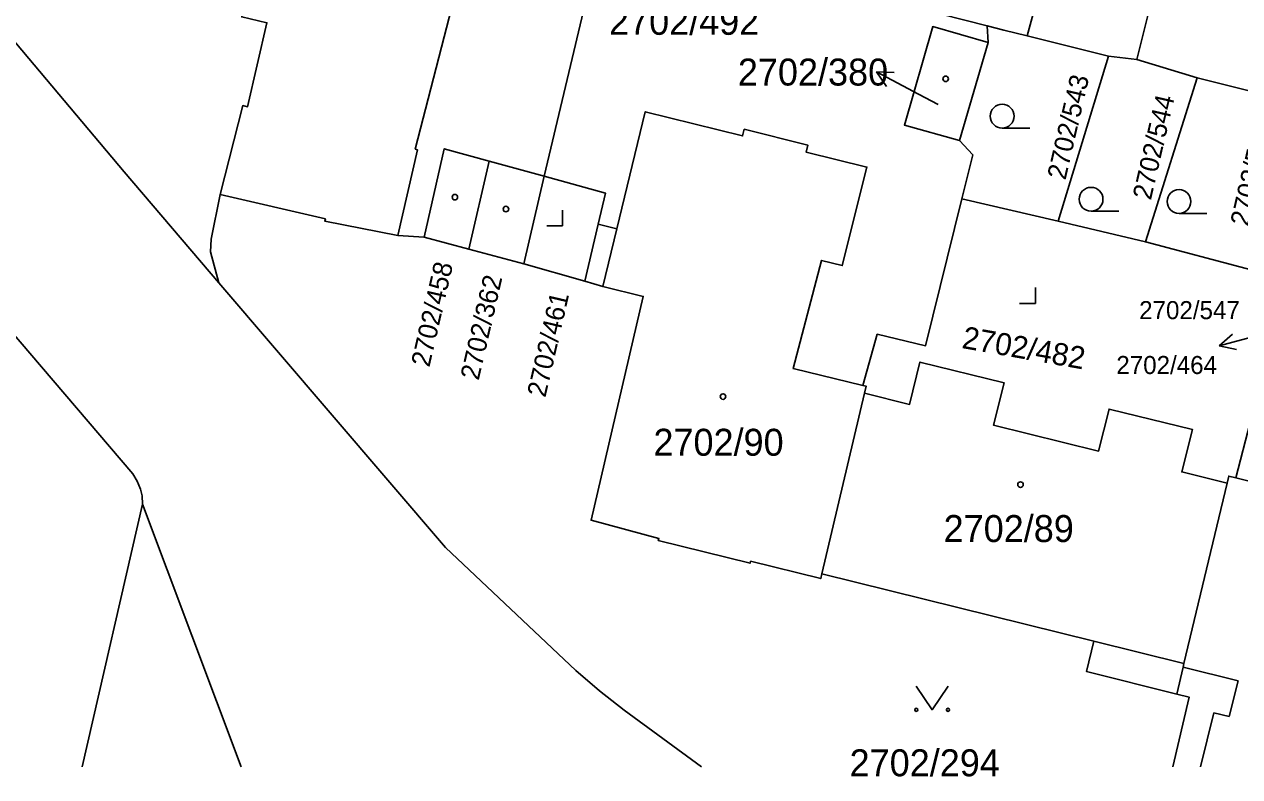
# Model space of a CAD drawing. Extents: x -496682 to -495776, y -1088797 to -1088018.
# Drawn here: x -496634.1 to -496557.4, y -1088570.1 to -1088522.6 of the extents above; entities that cross this region are included whole.
import ezdxf

# ---------------------------------------------------------------- set-up
doc = ezdxf.new("R2010")
doc.units = 0
for name, color, linetype in [('Hranice parcel', 7, 'Continuous'), ('Parcelní čísla', 7, 'Continuous'), ('Pop  PČ popisy', 7, 'Continuous'), ('Vnitřní kresba', 7, 'Continuous'), ('Značky budov', 7, 'Continuous'), ('Značky kultur', 7, 'Continuous')]:
    doc.layers.add(name, color=color, linetype=linetype)

msp = doc.modelspace()

# ---------------------------------------------------------------- linework, layer by layer
at = {"layer": 'Hranice parcel'}
for p, q in [((-496570.83, -1088523.36), (-496567.27, -1088510.42)), ((-496560.68, -1088512.06), (-496563.91, -1088524.85)), ((-496601.3, -1088532.22), (-496597.58, -1088516.58)), ((-496573.34, -1088522.74), (-496577.74, -1088521.62)), ((-496573.29, -1088523.79), (-496573.34, -1088522.74)), ((-496575.1, -1088529.97), (-496573.29, -1088523.79)), ((-496570.83, -1088523.36), (-496565.69, -1088524.64)), ((-496568.87, -1088535.04), (-496565.69, -1088524.64)), ((-496565.69, -1088524.64), (-496563.91, -1088524.85)), ((-496563.91, -1088524.85), (-496560.1, -1088526.02)), ((-496563.36, -1088536.35), (-496560.1, -1088526.02)), ((-496604.78, -1088531.26), (-496606.06, -1088536.81)), ((-496604.78, -1088531.26), (-496601.3, -1088532.22)), ((-496602.58, -1088537.75), (-496601.3, -1088532.22)), ((-496568.87, -1088535.04), (-496574.95, -1088533.64)), ((-496563.36, -1088536.35), (-496568.87, -1088535.04)), ((-496627.27, -1088550.98), (-496639.82, -1088536.3)), ((-496606.06, -1088536.81), (-496608.87, -1088536.05)), ((-496602.58, -1088537.75), (-496606.06, -1088536.81)), ((-496598.73, -1088538.84), (-496602.58, -1088537.75)), ((-496597.6, -1088539.16), (-496598.73, -1088538.84)), ((-496581.09, -1088545.9), (-496583.78, -1088557.29)), ((-496557.65, -1088551.23), (-496556.76, -1088547.74)), ((-496630.453, -1088569.448), (-496626.65, -1088552.9)), ((-496626.65, -1088552.9), (-496620.418, -1088569.448))]:
    msp.add_line(p, q, dxfattribs=at)
for points in [[(-496621.83, -1088538.93), (-496627.8, -1088531.94), (-496637.3, -1088520.68), (-496644.5, -1088512.3)], [(-496619.55, -1088518.48), (-496620.39, -1088522.17), (-496618.8, -1088522.54), (-496620.02, -1088527.84), (-496620.32, -1088527.76), (-496621.75, -1088533.36)], [(-496573.29, -1088523.79), (-496576.78, -1088522.78), (-496578.57, -1088528.99), (-496575.1, -1088529.97)], [(-496573.34, -1088522.74), (-496572.3, -1088523), (-496570.83, -1088523.36)], [(-496560.1, -1088526.02), (-496554.29, -1088527.46), (-496556.58, -1088537.69)], [(-496581.19, -1088545.41), (-496585.6, -1088544.35), (-496583.81, -1088537.52), (-496582.49, -1088537.85), (-496580.94, -1088531.64), (-496584.78, -1088530.69), (-496584.67, -1088530.25), (-496588.68, -1088529.26), (-496588.78, -1088529.68), (-496594.93, -1088528.15), (-496596.72, -1088535.54), (-496597.6, -1088539.16)], [(-496574.95, -1088533.64), (-496574.26, -1088530.86), (-496575.1, -1088529.97)], [(-496608.87, -1088536.05), (-496607.61, -1088530.48), (-496604.78, -1088531.26)], [(-496598.73, -1088538.84), (-496597.9, -1088535.25), (-496597.44, -1088533.28), (-496601.3, -1088532.22)], [(-496621.75, -1088533.36), (-496622.32, -1088536.19), (-496622.36, -1088536.99), (-496621.83, -1088538.93)], [(-496621.75, -1088533.36), (-496615.11, -1088534.91), (-496615.15, -1088535.05), (-496610.53, -1088535.95), (-496608.87, -1088536.05)], [(-496574.95, -1088533.64), (-496577.24, -1088542.91), (-496580.28, -1088542.18), (-496581.19, -1088545.41)], [(-496556.58, -1088537.69), (-496556.68, -1088538.12), (-496563.36, -1088536.35)], [(-496591.366, -1088569.448), (-496596.26, -1088565.89), (-496597.82, -1088564.67), (-496599.31, -1088563.38), (-496607.53, -1088555.63), (-496621.83, -1088538.93)], [(-496597.6, -1088539.16), (-496595.05, -1088539.8), (-496598.34, -1088553.91), (-496594.06, -1088555.06), (-496594.1, -1088555.19), (-496588.31, -1088556.62), (-496588.28, -1088556.49), (-496583.85, -1088557.58), (-496583.78, -1088557.29)], [(-496558.21, -1088551.57), (-496561.07, -1088550.86), (-496560.39, -1088548.19), (-496565.66, -1088546.9), (-496566.32, -1088549.55), (-496572.95, -1088547.91), (-496572.27, -1088545.25), (-496577.59, -1088543.93), (-496578.25, -1088546.6), (-496581.09, -1088545.9)], [(-496581.09, -1088545.9), (-496580.98, -1088545.46), (-496581.19, -1088545.41)], [(-496626.65, -1088552.9), (-496626.679, -1088552.359), (-496626.773, -1088551.939), (-496626.977, -1088551.436), (-496627.27, -1088550.98)], [(-496558.21, -1088551.57), (-496560.94, -1088562.93), (-496560.99, -1088563.18), (-496561.39, -1088564.87)], [(-496557.65, -1088551.23), (-496558.1, -1088551.12), (-496558.21, -1088551.57)], [(-496545.502, -1088569.448), (-496545.94, -1088569.34), (-496542.39, -1088555.02), (-496557.65, -1088551.23)], [(-496583.78, -1088557.29), (-496566.62, -1088561.53), (-496567.09, -1088563.44), (-496561.39, -1088564.87)], [(-496561.39, -1088564.87), (-496560.6, -1088565.07), (-496561.63, -1088569.448)]]:
    msp.add_lwpolyline(points, dxfattribs=at)
at = {"layer": 'Pop  PČ popisy'}
for p, q in [((-496577.69, -1088527.05), (-496580.34, -1088525.641)), ((-496580.34, -1088525.641), (-496579.22, -1088525.669)), ((-496580.34, -1088525.641), (-496579.691, -1088526.553)), ((-496576.45, -1088527.7), (-496577.69, -1088527.05)), ((-496555.81, -1088542.14), (-496558.709, -1088542.917)), ((-496558.709, -1088542.917), (-496557.871, -1088542.174)), ((-496558.709, -1088542.917), (-496557.612, -1088543.141))]:
    msp.add_line(p, q, dxfattribs=at)
at = {"layer": 'Vnitřní kresba'}
for p, q in [((-496605.65, -1088515.77), (-496609.45, -1088530.51)), ((-496609.3, -1088530.55), (-496610.53, -1088535.95)), ((-496609.45, -1088530.51), (-496609.3, -1088530.55)), ((-496597.9, -1088535.25), (-496596.72, -1088535.54)), ((-496560.94, -1088562.93), (-496566.62, -1088561.53)), ((-496560.99, -1088563.18), (-496557.51, -1088564.04)), ((-496557.51, -1088564.04), (-496558.07, -1088566.28)), ((-496559.04, -1088566.04), (-496559.88, -1088569.448)), ((-496558.07, -1088566.28), (-496559.04, -1088566.04))]:
    msp.add_line(p, q, dxfattribs=at)
at = {"layer": 'Značky budov'}
for centre in [(-496575.967, -1088526.079), (-496606.937, -1088533.539), (-496603.717, -1088534.289), (-496590.017, -1088546.109), (-496571.247, -1088551.659)]:
    msp.add_circle(centre, 0.175, dxfattribs=at)
at = {"layer": 'Značky kultur'}
for p, q in [((-496572.403, -1088529.18), (-496570.653, -1088529.18)), ((-496600.14, -1088535.35), (-496600.14, -1088534.35)), ((-496566.793, -1088534.42), (-496565.043, -1088534.42)), ((-496561.243, -1088534.56), (-496559.493, -1088534.56)), ((-496601.141, -1088535.35), (-496600.14, -1088535.35)), ((-496570.3, -1088540.24), (-496570.3, -1088539.24)), ((-496571.301, -1088540.24), (-496570.3, -1088540.24))]:
    msp.add_line(p, q, dxfattribs=at)
msp.add_lwpolyline([(-496577.82, -1088564.359), (-496576.82, -1088565.86), (-496575.82, -1088564.359)], dxfattribs=at)
for centre, radius in [((-496572.403, -1088528.43), 0.75), ((-496566.793, -1088533.67), 0.75), ((-496561.243, -1088533.81), 0.75), ((-496577.82, -1088565.859), 0.1), ((-496575.82, -1088565.859), 0.1)]:
    msp.add_circle(centre, radius, dxfattribs=at)

# ---------------------------------------------------------------- texts
at = {"layer": 'Parcelní čísla'}
for s, height, p in [('2702/492', 1.7, (-496597.21, -1088523.3)), ('2702/380', 1.7, (-496589.08, -1088526.5)), ('2702/547', 1.139, (-496563.758, -1088541.229)), ('2702/464', 1.139, (-496565.198, -1088544.689)), ('2702/90', 1.7, (-496594.408, -1088549.84)), ('2702/89', 1.7, (-496576.098, -1088555.28)), ('2702/294', 1.7, (-496582.03, -1088570.05))]:
    msp.add_text(s, height=height, dxfattribs=at).set_placement(p)
for s, height, rotation, p in [('2702/543', 1.2, 77, (-496568.409, -1088532.5)), ('2702/544', 1.2, 77, (-496563.019, -1088533.77)), ('2702/545', 1.2, 77, (-496556.859, -1088535.43)), ('2702/458', 1.2, 77, (-496608.549, -1088544.3)), ('2702/362', 1.2, 77, (-496605.439, -1088545.13)), ('2702/461', 1.2, 77, (-496601.229, -1088546.21)), ('2702/482', 1.401, 350, (-496574.998, -1088543.044))]:
    msp.add_text(s, height=height, rotation=rotation, dxfattribs=at).set_placement(p)

doc.saveas('drawing.dxf')
